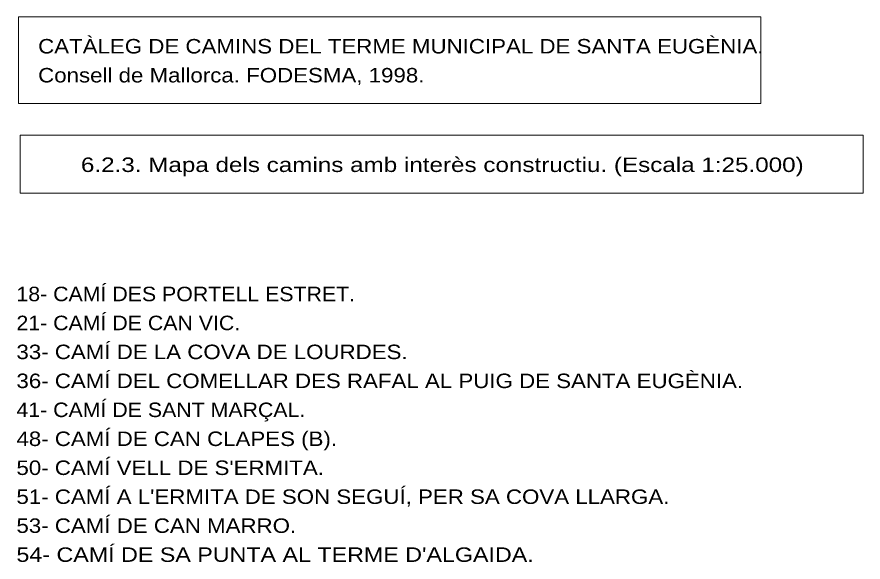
# Model space of a CAD drawing. Extents: x 476989 to 498418, y 4381813 to 4416555.
# Drawn here: x 480306 to 483226, y 4387035 to 4388918 of the extents above; entities that cross this region are included whole.
import ezdxf
from ezdxf.enums import TextEntityAlignment as Align

# ---------------------------------------------------------------- set-up
doc = ezdxf.new("R2010")
doc.units = 0
doc.header["$LTSCALE"] = 20
doc.layers.add('13', color=7, linetype='Continuous', lineweight=13)

msp = doc.modelspace()

# ---------------------------------------------------------------- linework, layer by layer
at = {"layer": '13'}
for points in [[(480311.63, 4388917.52), (482873.59, 4388917.52), (482873.59, 4388618.76), (480311.63, 4388618.76)], [(480316.85, 4388508.69), (483226.38, 4388508.69), (483226.38, 4388309.52), (480316.85, 4388309.52)]]:
    msp.add_lwpolyline(points, close=True, dxfattribs=at)

# ---------------------------------------------------------------- texts
for s, width, p in [('CATÀLEG DE CAMINS DEL TERME MUNICIPAL DE SANTA EUGÈNIA.', 1.15, (480379.02, 4388791.28)), ('Consell de Mallorca. FODESMA, 1998.', 1.15, (480379.02, 4388691.28)), ('18- CAMÍ DES PORTELL ESTRET.', 1.1, (480304.16, 4387935.98)), ('21- CAMÍ DE CAN VIC.', 1.1, (480304.16, 4387835.98)), ('33- CAMÍ DE LA COVA DE LOURDES.', 1.15, (480304.16, 4387735.98)), ('36- CAMÍ DEL COMELLAR DES RAFAL AL PUIG DE SANTA EUGÈNIA.', 1.15, (480304.16, 4387635.98)), ('41- CAMÍ DE SANT MARÇAL.', 1.1, (480304.16, 4387535.98)), ('48- CAMÍ DE CAN CLAPES (B).', 1.15, (480304.16, 4387435.98)), ("50- CAMÍ VELL DE S'ERMITA.", 1.15, (480304.16, 4387335.98)), ("51- CAMÍ A L'ERMITA DE SON SEGUÍ, PER SA COVA LLARGA.", 1.15, (480304.16, 4387235.98)), ('53- CAMÍ DE CAN MARRO.', 1.15, (480304.16, 4387135.98)), ("54- CAMÍ DE SA PUNTA AL TERME D'ALGAIDA.", 1.2, (480304.16, 4387035.98))]:
    msp.add_text(s, height=50, dxfattribs=dict(at, width=width)).set_placement(p)
at = {"layer": '13', "width": 1.25}
msp.add_text('6.2.3. Mapa dels camins amb interès constructiu. (Escala 1:25.000)', height=50, dxfattribs=at).set_placement((481774.05, 4388382.09), align=Align.CENTER)

doc.saveas('drawing.dxf')
